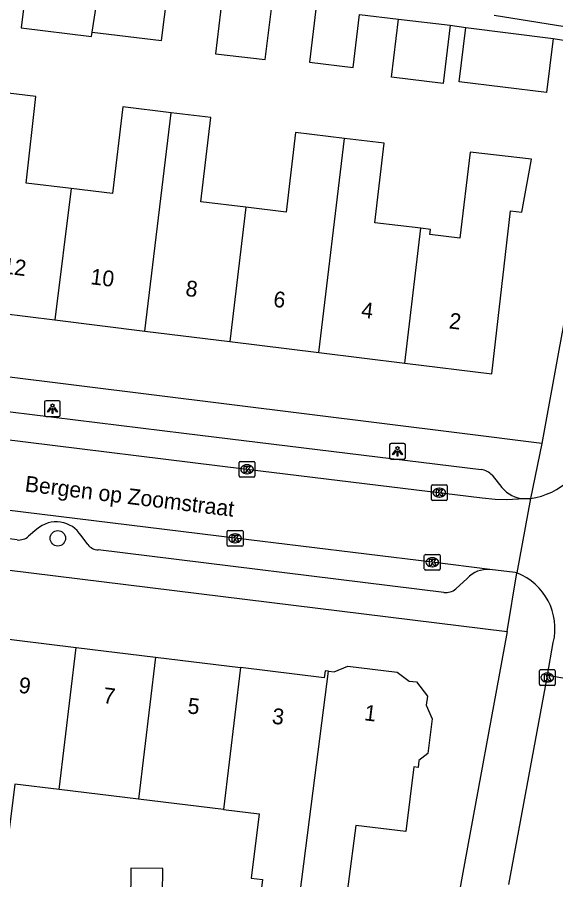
# Model space of a CAD drawing. Extents: x 158087 to 159494, y 382905 to 383981.
# Drawn here: x 158526.2 to 158560.2, y 383221.8 to 383276.3 of the extents above; entities that cross this region are included whole.
import ezdxf

# ---------------------------------------------------------------- set-up
doc = ezdxf.new("R2010")
doc.units = 0
for name, color, linetype in [('IMGEO_Boom', 7, 'Continuous'), ('IMGEO_Kolk', 7, 'Continuous'), ('IMGEO_Lichtpunt', 7, 'Continuous'), ('IMGEO_Openbare_ruimte_label', 7, 'Continuous'), ('IMGEO_Pand', 7, 'Continuous'), ('IMGEO_Pand_nummerreeks', 7, 'Continuous'), ('IMGEO_Rijbaan_lokaal_open', 7, 'Continuous'), ('IMGEO_Voetpad_open', 7, 'Continuous')]:
    doc.layers.add(name, color=color, linetype=linetype)

msp = doc.modelspace()

# ---------------------------------------------------------------- linework, layer by layer
at = {"layer": 'IMGEO_Boom'}
msp.add_circle((158528.736, 383243.352), 0.489, dxfattribs=at)
at = {"layer": 'IMGEO_Kolk'}
for p, q in [((158540.2, 383247.29), (158540.2, 383248.142)), ((158540.275, 383248.216), (158541.127, 383248.216)), ((158540.688, 383247.996), (158540.713, 383247.996)), ((158541.201, 383248.142), (158541.201, 383247.29)), ((158540.711, 383247.436), (158540.686, 383247.436)), ((158541.127, 383247.216), (158540.275, 383247.216)), ((158552.435, 383246.733), (158553.287, 383246.733)), ((158552.36, 383245.807), (158552.36, 383246.659)), ((158552.848, 383246.513), (158552.873, 383246.513)), ((158553.361, 383246.659), (158553.361, 383245.807)), ((158553.287, 383245.733), (158552.435, 383245.733)), ((158552.871, 383245.953), (158552.846, 383245.953)), ((158539.448, 383242.924), (158539.448, 383243.776)), ((158539.523, 383243.85), (158540.375, 383243.85)), ((158539.936, 383243.63), (158539.961, 383243.63)), ((158540.449, 383243.776), (158540.449, 383242.924)), ((158539.959, 383243.07), (158539.934, 383243.07)), ((158540.375, 383242.85), (158539.523, 383242.85)), ((158551.989, 383242.335), (158552.841, 383242.335)), ((158551.914, 383241.409), (158551.914, 383242.261)), ((158552.402, 383242.115), (158552.427, 383242.115)), ((158552.915, 383242.261), (158552.915, 383241.409)), ((158552.841, 383241.335), (158551.989, 383241.335)), ((158552.425, 383241.555), (158552.4, 383241.555)), ((158559.189, 383234.117), (158559.189, 383234.969)), ((158559.264, 383235.043), (158560.116, 383235.043)), ((158559.677, 383234.823), (158559.702, 383234.823)), ((158560.19, 383234.969), (158560.19, 383234.117)), ((158559.7, 383234.263), (158559.675, 383234.263)), ((158560.116, 383234.043), (158559.264, 383234.043))]:
    msp.add_line(p, q, dxfattribs=at)
for points in [[(158540.2, 383247.29), (158540.2, 383248.142)], [(158540.275, 383248.216), (158541.127, 383248.216)], [(158540.521, 383247.916), (158540.644, 383247.916), (158540.644, 383247.765), (158540.774, 383247.916), (158540.938, 383247.916), (158540.792, 383247.765), (158540.945, 383247.516), (158540.793, 383247.516), (158540.708, 383247.68), (158540.644, 383247.613), (158540.644, 383247.516), (158540.521, 383247.516), (158540.521, 383247.916)], [(158541.201, 383248.142), (158541.201, 383247.29)], [(158541.127, 383247.216), (158540.275, 383247.216)], [(158552.435, 383246.733), (158553.287, 383246.733)], [(158552.36, 383245.807), (158552.36, 383246.659)], [(158552.681, 383246.433), (158552.804, 383246.433), (158552.804, 383246.282), (158552.934, 383246.433), (158553.098, 383246.433), (158552.952, 383246.282), (158553.105, 383246.033), (158552.953, 383246.033), (158552.868, 383246.197), (158552.804, 383246.13), (158552.804, 383246.033), (158552.681, 383246.033), (158552.681, 383246.433)], [(158553.361, 383246.659), (158553.361, 383245.807)], [(158553.287, 383245.733), (158552.435, 383245.733)], [(158539.448, 383242.924), (158539.448, 383243.776)], [(158539.523, 383243.85), (158540.375, 383243.85)], [(158539.769, 383243.55), (158539.892, 383243.55), (158539.892, 383243.399), (158540.022, 383243.55), (158540.186, 383243.55), (158540.04, 383243.399), (158540.193, 383243.15), (158540.041, 383243.15), (158539.956, 383243.314), (158539.892, 383243.247), (158539.892, 383243.15), (158539.769, 383243.15), (158539.769, 383243.55)], [(158540.449, 383243.776), (158540.449, 383242.924)], [(158540.375, 383242.85), (158539.523, 383242.85)], [(158551.989, 383242.335), (158552.841, 383242.335)], [(158551.914, 383241.409), (158551.914, 383242.261)], [(158552.235, 383242.035), (158552.358, 383242.035), (158552.358, 383241.884), (158552.488, 383242.035), (158552.652, 383242.035), (158552.506, 383241.884), (158552.659, 383241.635), (158552.507, 383241.635), (158552.422, 383241.799), (158552.358, 383241.732), (158552.358, 383241.635), (158552.235, 383241.635), (158552.235, 383242.035)], [(158552.915, 383242.261), (158552.915, 383241.409)], [(158552.841, 383241.335), (158551.989, 383241.335)], [(158559.189, 383234.117), (158559.189, 383234.969)], [(158559.264, 383235.043), (158560.116, 383235.043)], [(158559.51, 383234.743), (158559.633, 383234.743), (158559.633, 383234.592), (158559.763, 383234.743), (158559.927, 383234.743), (158559.781, 383234.592), (158559.934, 383234.343), (158559.782, 383234.343), (158559.697, 383234.507), (158559.633, 383234.44), (158559.633, 383234.343), (158559.51, 383234.343), (158559.51, 383234.743)], [(158560.19, 383234.969), (158560.19, 383234.117)], [(158560.116, 383234.043), (158559.264, 383234.043)]]:
    msp.add_lwpolyline(points, dxfattribs=at)
for centre, start, end in [((158540.277, 383248.14), 91.552, 178.448), ((158540.277, 383248.14), 91.552, 178.448), ((158541.125, 383248.14), 1.552, 88.448), ((158541.125, 383248.14), 1.552, 88.448), ((158540.277, 383247.292), 181.552, 268.448), ((158540.277, 383247.292), 181.552, 268.448), ((158541.125, 383247.292), 271.552, 358.448), ((158541.125, 383247.292), 271.552, 358.448), ((158552.437, 383246.657), 91.552, 178.448), ((158552.437, 383246.657), 91.552, 178.448), ((158553.285, 383246.657), 1.552, 88.448), ((158553.285, 383246.657), 1.552, 88.448), ((158552.437, 383245.809), 181.552, 268.448), ((158552.437, 383245.809), 181.552, 268.448), ((158553.285, 383245.809), 271.552, 358.448), ((158553.285, 383245.809), 271.552, 358.448), ((158539.525, 383243.774), 91.552, 178.448), ((158539.525, 383243.774), 91.552, 178.448), ((158540.373, 383243.774), 1.552, 88.448), ((158540.373, 383243.774), 1.552, 88.448), ((158539.525, 383242.926), 181.552, 268.448), ((158539.525, 383242.926), 181.552, 268.448), ((158540.373, 383242.926), 271.552, 358.448), ((158540.373, 383242.926), 271.552, 358.448), ((158551.991, 383242.259), 91.552, 178.448), ((158551.991, 383242.259), 91.552, 178.448), ((158552.839, 383242.259), 1.552, 88.448), ((158552.839, 383242.259), 1.552, 88.448), ((158551.991, 383241.411), 181.552, 268.448), ((158551.991, 383241.411), 181.552, 268.448), ((158552.839, 383241.411), 271.552, 358.448), ((158552.839, 383241.411), 271.552, 358.448), ((158559.266, 383234.967), 91.552, 178.448), ((158559.266, 383234.967), 91.552, 178.448), ((158560.114, 383234.967), 1.552, 88.448), ((158560.114, 383234.967), 1.552, 88.448), ((158559.266, 383234.119), 181.552, 268.448), ((158559.266, 383234.119), 181.552, 268.448), ((158560.114, 383234.119), 271.552, 358.448), ((158560.114, 383234.119), 271.552, 358.448)]:
    msp.add_arc(centre, 0.0765, start, end, dxfattribs=at)
for centre, major_axis, ratio, start_param, end_param in [((158540.687, 383247.716), (-0.387, 0.002), 0.722429, 4.712389, 7.853982), ((158540.712, 383247.716), (-0.39, 0.002), 0.717154, 1.570796, 4.712389), ((158552.847, 383246.233), (-0.387, 0.002), 0.722429, 4.712389, 7.853982), ((158552.872, 383246.233), (-0.39, 0.002), 0.717154, 1.570796, 4.712389), ((158539.935, 383243.35), (-0.387, 0.002), 0.722429, 4.712389, 7.853982), ((158539.96, 383243.35), (-0.39, 0.002), 0.717154, 1.570796, 4.712389), ((158552.401, 383241.835), (-0.387, 0.002), 0.722429, 4.712389, 7.853982), ((158552.426, 383241.835), (-0.39, 0.002), 0.717154, 1.570796, 4.712389), ((158559.676, 383234.543), (-0.387, 0.002), 0.722429, 4.712389, 7.853982), ((158559.701, 383234.543), (-0.39, 0.002), 0.717154, 1.570796, 4.712389)]:
    msp.add_ellipse(centre, major_axis=major_axis, ratio=ratio, start_param=start_param, end_param=end_param, dxfattribs=at)
at = {"layer": 'IMGEO_Lichtpunt'}
for p, q in [((158527.896, 383251.95), (158527.896, 383251.143)), ((158527.896, 383251.95), (158527.896, 383251.143)), ((158528.798, 383252.045), (158527.99, 383252.045)), ((158528.798, 383252.045), (158527.99, 383252.045)), ((158528.892, 383251.143), (158528.892, 383251.95)), ((158528.892, 383251.143), (158528.892, 383251.95)), ((158527.99, 383251.049), (158528.798, 383251.049)), ((158527.99, 383251.049), (158528.798, 383251.049)), ((158549.717, 383249.251), (158549.717, 383248.444)), ((158549.717, 383249.251), (158549.717, 383248.444)), ((158550.619, 383249.346), (158549.811, 383249.346)), ((158550.619, 383249.346), (158549.811, 383249.346)), ((158550.713, 383248.444), (158550.713, 383249.251)), ((158550.713, 383248.444), (158550.713, 383249.251)), ((158549.811, 383248.35), (158550.619, 383248.35)), ((158549.811, 383248.35), (158550.619, 383248.35))]:
    msp.add_line(p, q, dxfattribs=at)
for points in [[(158528.27, 383251.614), (158528.309, 383251.586), (158528.121, 383251.324), (158528.083, 383251.351), (158528.27, 383251.614)], [(158528.482, 383251.586), (158528.52, 383251.613), (158528.707, 383251.351), (158528.668, 383251.323), (158528.482, 383251.586)], [(158528.372, 383251.566), (158528.419, 383251.566), (158528.419, 383251.244), (158528.372, 383251.244), (158528.372, 383251.566)], [(158550.091, 383248.915), (158550.13, 383248.887), (158549.942, 383248.625), (158549.904, 383248.652), (158550.091, 383248.915)], [(158550.303, 383248.887), (158550.341, 383248.914), (158550.528, 383248.652), (158550.489, 383248.624), (158550.303, 383248.887)], [(158550.193, 383248.867), (158550.24, 383248.867), (158550.24, 383248.545), (158550.193, 383248.545), (158550.193, 383248.867)]]:
    msp.add_lwpolyline(points, dxfattribs=at)
for centre in [(158528.395, 383251.748), (158550.216, 383249.049)]:
    msp.add_circle(centre, 0.0994, dxfattribs=at)
for centre, start, end in [((158527.99, 383251.95), 90, 180), ((158527.99, 383251.95), 90, 180), ((158528.798, 383251.95), 0, 90), ((158528.798, 383251.95), 0, 90), ((158527.99, 383251.143), 180, 270), ((158527.99, 383251.143), 180, 270), ((158528.798, 383251.143), 270, 0), ((158528.798, 383251.143), 270, 360), ((158549.811, 383249.251), 90, 180), ((158549.811, 383249.251), 90, 180), ((158550.619, 383249.251), 0, 90), ((158550.619, 383249.251), 0, 90), ((158549.811, 383248.444), 180, 270), ((158549.811, 383248.444), 180, 270), ((158550.619, 383248.444), 270, 0), ((158550.619, 383248.444), 270, 360)]:
    msp.add_arc(centre, 0.0946, start, end, dxfattribs=at)
at = {"layer": 'IMGEO_Pand'}
for points in [[(158526.839, 383279.064), (158526.416, 383275.634), (158530.874, 383275.085), (158530.915, 383275.361)], [(158530.915, 383275.361), (158531.368, 383278.375)], [(158530.915, 383275.361), (158535.287, 383274.821), (158535.661, 383277.846)], [(158539.134, 383277.539), (158538.709, 383273.995), (158541.856, 383273.618), (158542.281, 383277.159)], [(158545.05, 383276.81), (158544.646, 383273.459), (158547.409, 383273.127), (158547.812, 383276.478)], [(158553.55, 383275.789), (158553.109, 383272.112), (158549.846, 383272.504), (158550.288, 383276.18)], [(158550.288, 383276.18), (158553.55, 383275.789)], [(158560.056, 383274.966), (158559.631, 383271.534), (158554.123, 383272.215), (158554.548, 383275.647)], [(158554.548, 383275.647), (158560.056, 383274.966)], [(158529.577, 383265.474), (158526.723, 383265.818), (158527.351, 383271.291), (158524.878, 383271.588)], [(158535.898, 383270.264), (158532.854, 383270.63), (158532.194, 383265.159), (158529.577, 383265.474)], [(158534.234, 383256.458), (158535.898, 383270.264)], [(158540.63, 383264.283), (158537.773, 383264.627), (158538.416, 383269.961), (158535.898, 383270.264)], [(158546.868, 383268.639), (158543.774, 383269.011), (158543.168, 383263.977), (158540.63, 383264.283)], [(158545.237, 383255.102), (158546.868, 383268.639)], [(158551.701, 383262.953), (158548.777, 383263.305), (158549.383, 383268.336), (158546.868, 383268.639)], [(158550.674, 383254.432), (158556.179, 383253.753), (158557.368, 383264.068), (158558.075, 383263.983), (158558.683, 383267.326), (158554.807, 383267.76), (158554.162, 383262.326), (158552.257, 383262.555), (158552.296, 383262.881), (158551.701, 383262.953)], [(158529.577, 383265.474), (158528.551, 383257.159)], [(158540.63, 383264.283), (158539.607, 383255.796)], [(158550.674, 383254.432), (158551.701, 383262.953)], [(158523.4, 383257.793), (158528.551, 383257.159)], [(158528.551, 383257.159), (158534.234, 383256.458)], [(158534.234, 383256.458), (158539.607, 383255.796)], [(158539.607, 383255.796), (158545.237, 383255.102)], [(158545.237, 383255.102), (158550.674, 383254.432)], [(158524.404, 383237.115), (158529.904, 383236.444)], [(158528.82, 383227.467), (158529.904, 383236.444)], [(158529.904, 383236.444), (158534.922, 383235.832)], [(158534.922, 383235.832), (158533.838, 383226.852)], [(158534.922, 383235.832), (158540.289, 383235.178)], [(158545.85, 383234.951), (158546.215, 383234.906), (158547.08, 383235.274), (158550.194, 383234.893), (158550.954, 383234.319), (158551.418, 383234.263), (158552.106, 383233.362), (158552.038, 383232.806), (158552.408, 383231.936), (158552.139, 383229.739), (158551.576, 383229.299), (158551.522, 383228.858), (158551.252, 383228.891), (158550.752, 383224.802), (158547.576, 383225.192), (158546.619, 383217.77)], [(158540.289, 383235.178), (158539.205, 383226.195)], [(158545.85, 383234.951), (158545.636, 383234.977), (158545.582, 383234.532), (158540.289, 383235.178)], [(158543.707, 383218.146), (158544.884, 383227.374), (158545.85, 383234.951)], [(158528.82, 383227.467), (158526.013, 383227.811), (158525.575, 383224.232), (158522.887, 383224.556), (158522.96, 383225.163), (158523.32, 383228.141)], [(158533.838, 383226.852), (158528.82, 383227.467)], [(158539.205, 383226.195), (158533.838, 383226.852)], [(158539.205, 383226.195), (158541.465, 383225.918), (158540.968, 383221.862), (158541.676, 383221.775), (158541.142, 383217.415)], [(158533.395, 383217.563), (158535.323, 383217.542), (158535.376, 383222.46), (158533.36, 383222.482), (158533.31, 383217.88)]]:
    msp.add_lwpolyline(points, dxfattribs=at)
at = {"layer": 'IMGEO_Rijbaan_lokaal_open'}
for points in [[(158508.865, 383251.607), (158511.166, 383251.332), (158515.542, 383250.802), (158522.118, 383250), (158524.966, 383249.656), (158540.697, 383247.714), (158555.572, 383245.902), (158556.395, 383245.816), (158557.139, 383245.805), (158558.233, 383245.857)], [(158556.058, 383241.376), (158552.411, 383241.836), (158539.945, 383243.351), (158524.296, 383245.269), (158506.597, 383247.359)], [(158558.62, 383245.875), (158557.763, 383241.156)], [(158558.233, 383245.857), (158558.62, 383245.875)], [(158557.763, 383241.156), (158557.654, 383241.196), (158556.058, 383241.376)], [(158559.7, 383234.689), (158560.07, 383236.756)], [(158557.269, 383221.447), (158559.687, 383234.543), (158559.7, 383234.689)], [(158559.7, 383234.689), (158567.556, 383233.332)]]:
    msp.add_lwpolyline(points, dxfattribs=at)
for centre, radius, start, end in [((158558.059, 383250.272), 4.433, 277.2758, 349.4661), ((158556.414, 383237.644), 3.762, 346.3499, 68.9878)]:
    msp.add_arc(centre, radius, start, end, dxfattribs=at)
at = {"layer": 'IMGEO_Voetpad_open'}
for points in [[(158547.812, 383276.478), (158550.288, 383276.18)], [(158564.087, 383275.159), (158556.333, 383276.42)], [(158553.55, 383275.789), (158554.548, 383275.647)], [(158560.056, 383274.966), (158563.934, 383274.338)], [(158563.934, 383274.338), (158560.424, 383255.241), (158559.351, 383249.35)], [(158559.351, 383249.35), (158554.129, 383250), (158505.675, 383256.031)], [(158511.786, 383253.063), (158514.765, 383252.707), (158536.699, 383250), (158555.506, 383247.692)], [(158559.351, 383249.35), (158558.62, 383245.875)], [(158556.195, 383247.332), (158556.819, 383246.554)], [(158526.169, 383243.244), (158508.498, 383245.426)], [(158498.052, 383244.744), (158500, 383244.504), (158557.145, 383237.463)], [(158527.415, 383243.936), (158526.888, 383243.475)], [(158530.624, 383242.952), (158530.209, 383243.519)], [(158553.149, 383239.93), (158531.288, 383242.615)], [(158554.629, 383240.812), (158553.899, 383240.146)], [(158557.145, 383237.463), (158557.763, 383241.156)], [(158557.145, 383237.463), (158554.304, 383221.99), (158553.636, 383218.225)]]:
    msp.add_lwpolyline(points, dxfattribs=at)
for centre, radius, start, end in [((158555.398, 383246.646), 1.052, 40.7202, 84.106), ((158558.331, 383247.839), 1.985, 220.3596, 267.1604), ((158528.635, 383242.538), 1.855, 31.915, 131.1077), ((158526.241, 383244.254), 1.012, 265.9125, 309.7098), ((158531.319, 383243.498), 0.883, 218.1649, 268.0168), ((158555.907, 383239.667), 1.715, 84.9336, 138.1429), ((158553.269, 383240.925), 1.002, 263.1441, 308.9887)]:
    msp.add_arc(centre, radius, start, end, dxfattribs=at)

# ---------------------------------------------------------------- texts
at = {"layer": 'IMGEO_Openbare_ruimte_label'}
msp.add_text('Bergen op Zoomstraat', height=1, rotation=353.0526, dxfattribs=at).set_placement((158526.616, 383246.32))
at = {"layer": 'IMGEO_Pand_nummerreeks'}
for s, rotation, p in [('12', 352.9729, (158525.199, 383260.11)), ('10', 352.9729, (158530.761, 383259.425)), ('8', 352.9729, (158536.775, 383258.684)), ('6', 352.9729, (158542.326, 383258)), ('4', 352.9729, (158547.882, 383257.315)), ('2', 352.9729, (158553.435, 383256.631)), ('9', 353.0466, (158526.22, 383233.589)), ('7', 353.0466, (158531.561, 383232.938)), ('5', 353.0466, (158536.901, 383232.286)), ('3', 353.0443, (158542.242, 383231.635)), ('1', 353.0271, (158548.078, 383231.848))]:
    msp.add_text(s, height=1, rotation=rotation, dxfattribs=at).set_placement(p)

doc.saveas('drawing.dxf')
